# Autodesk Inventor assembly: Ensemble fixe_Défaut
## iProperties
Shininess: 64.0
Length Units: 11269
Angle Units: 11279
Time Units: 11290
Mass Units: 11283
Length Display Precision: 3
Angle Display Precision: 2
Compacted: True
Created: 2006-01
Part Number: Ensemble fixe_Défaut
Document SubType Name: Assembly
Designer: riri
Density: 0.0
Volumn: 0.0
Area: 0.0
PropertySet Name: Model Information
Control State: 0
Master: False
Checked Out: False
Author: riri
